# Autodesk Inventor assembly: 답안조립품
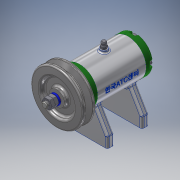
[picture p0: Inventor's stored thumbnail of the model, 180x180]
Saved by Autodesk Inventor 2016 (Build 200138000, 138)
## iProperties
Created: 2018-05
Part Number: 답안조립품
Material: 일반
Document SubType Name: Assembly
Designer: USER
Author: USER
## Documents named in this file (15)
- C:\Users\USER\Desktop\480507V1024\답안조립품.iam
- C:\Users\USER\Desktop\480507V1024\본체.ipt
- C:\Users\USER\Desktop\480507V1024\베어링 6002.ipt
- C:\Users\USER\Desktop\480507V1024\축.ipt
- C:\Users\USER\Desktop\480507V1024\키 3x3x12.ipt
- C:\Users\USER\Desktop\480507V1024\뒤커버.ipt
- C:\Users\USER\Desktop\480507V1024\볼트 M4x12.ipt
- C:\Users\USER\Desktop\480507V1024\앞커버.ipt
- C:\Users\USER\Desktop\480507V1024\V벨트풀리.ipt
- C:\Users\USER\Desktop\480507V1024\오일 실 15 25 7.ipt
- C:\Users\USER\Desktop\480507V1024\스프링와셔 8.ipt
- C:\Users\USER\Desktop\480507V1024\와셔 6x11.5.ipt
- C:\Users\USER\Desktop\480507V1024\너트 M8.ipt
- C:\Users\USER\Desktop\480507V1024\니플 M6x0.75.ipt
- C:\Users\USER\Desktop\480507V1024\볼트 M6x8.ipt
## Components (1 placed, 1 different names)
1. V벨트풀리:1
